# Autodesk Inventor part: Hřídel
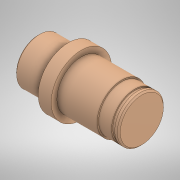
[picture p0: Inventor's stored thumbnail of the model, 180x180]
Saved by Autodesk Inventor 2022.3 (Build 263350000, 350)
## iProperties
Created: 2024-12
Part Number: Hřídel
Material: Všeobecné
Document SubType Name: Modeling
Designer: Hra42
Density: 1 g/cm^3
Appearance: Výchozí
Author: Hra42
Sending System: SolidWorks 2012
Last Author: Hra42
Last Saved: 2025-11-10
Source: hřídelka
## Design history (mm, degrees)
node "Hřídel.SLDPRT"
node "Těleso1"
feature "Zkosení2"
